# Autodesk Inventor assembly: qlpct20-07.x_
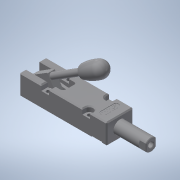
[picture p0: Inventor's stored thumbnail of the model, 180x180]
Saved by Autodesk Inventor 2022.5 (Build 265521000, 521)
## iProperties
Part Number: qlpct20-07.x_
Material: 一般
Document SubType Name: Assembly
Designer: ImaoCorp
Sending System: SOLIDWORKS 2017-2017317
MC: AMD64
MC_MODEL: Intel64 Family 6 Model 60 Stepping 3, GenuineIntel
OS: Windows_NT
FRU: Parasolid Version 29.0, build 201,  4-17-2017
FORMAT: text
GUISE: transmit
KEY: qlpct20-07
FILE: qlpct20-07.x_t
DATE: Wed Sep 04 15:45:25 2019
Author: ImaoCorp
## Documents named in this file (6)
- X:\14_SW2022-Inv2022\00_全2023-1023新製品(TCC)まで\q\qlpct20-07\QLPCT20-07.iam
- X:\14_SW2022-Inv2022\00_全2023-1023新製品(TCC)まで\q\qlpct20-07\qlpct20-07_01.ipt
- X:\14_SW2022-Inv2022\00_全2023-1023新製品(TCC)まで\q\qlpct20-07\qlpct20-07_02.ipt
- X:\14_SW2022-Inv2022\00_全2023-1023新製品(TCC)まで\q\qlpct20-07\qlpct20-07_03.ipt
- X:\14_SW2022-Inv2022\00_全2023-1023新製品(TCC)まで\q\qlpct20-07\qlpct20-07_04.ipt
- X:\14_SW2022-Inv2022\00_全2023-1023新製品(TCC)まで\q\qlpct20-07\qlpct20-07_05.ipt
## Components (5 placed, 5 different names)
1. qlpct20-07_01
2. qlpct20-07_02
3. qlpct20-07_03
4. qlpct20-07_04
5. qlpct20-07_05
